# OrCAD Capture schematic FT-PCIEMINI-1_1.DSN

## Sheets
1 INDEX: title: 01-INDEX; rev: 1.1
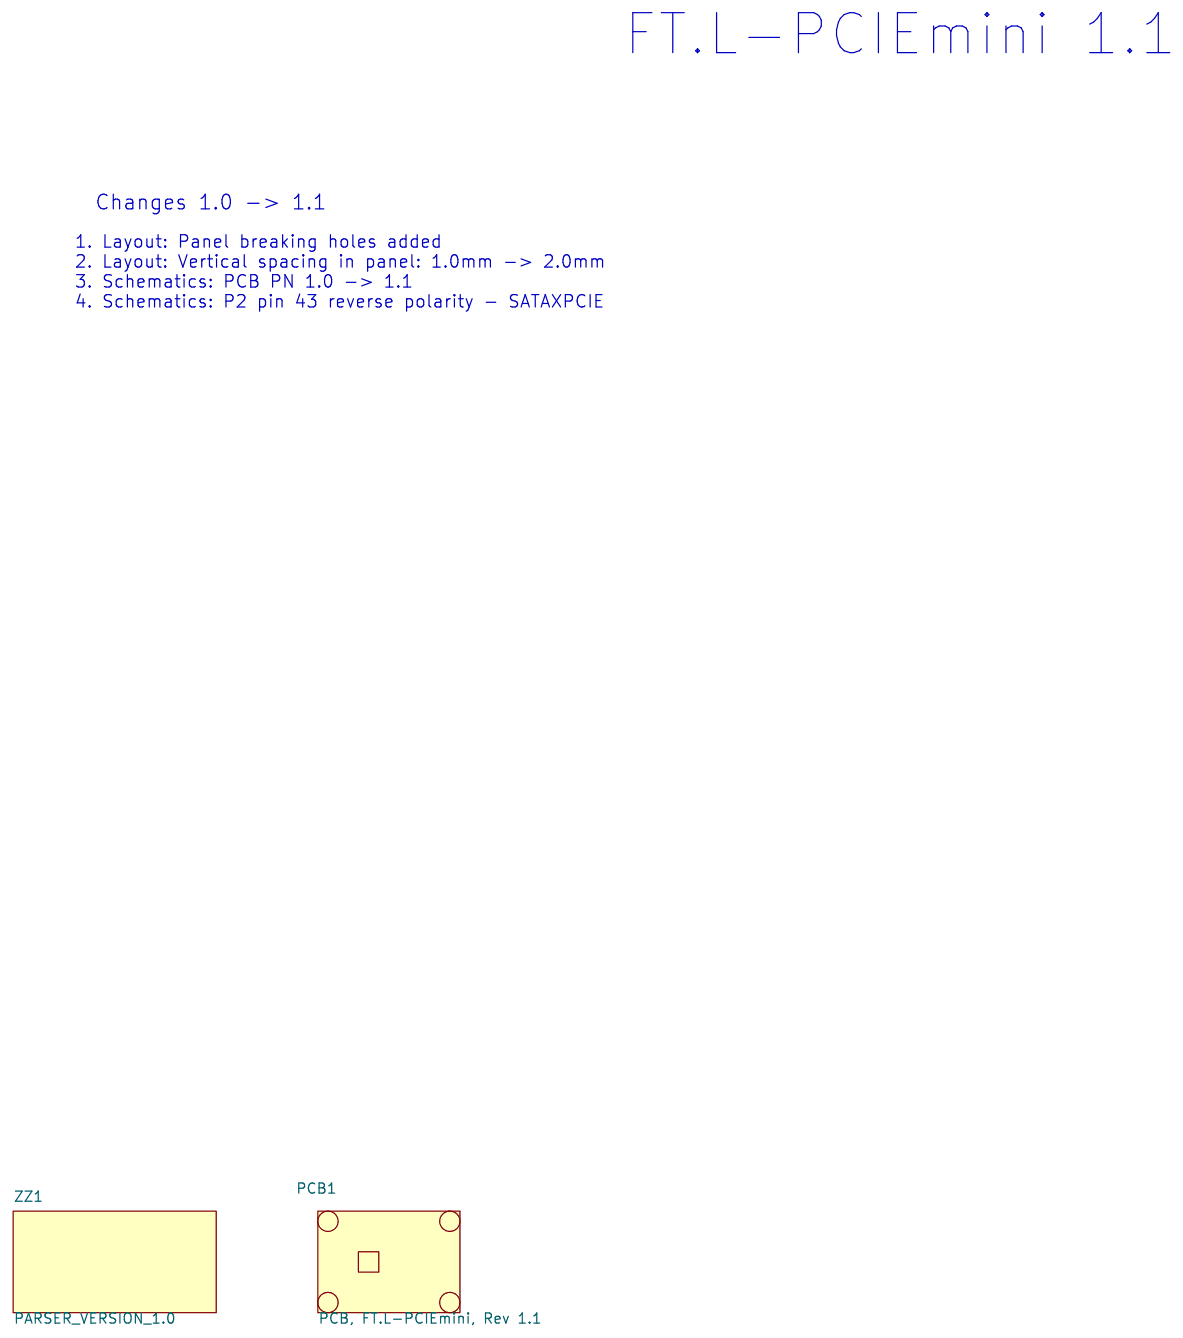
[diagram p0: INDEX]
2 TRIP: size A; title: 02-TRIP
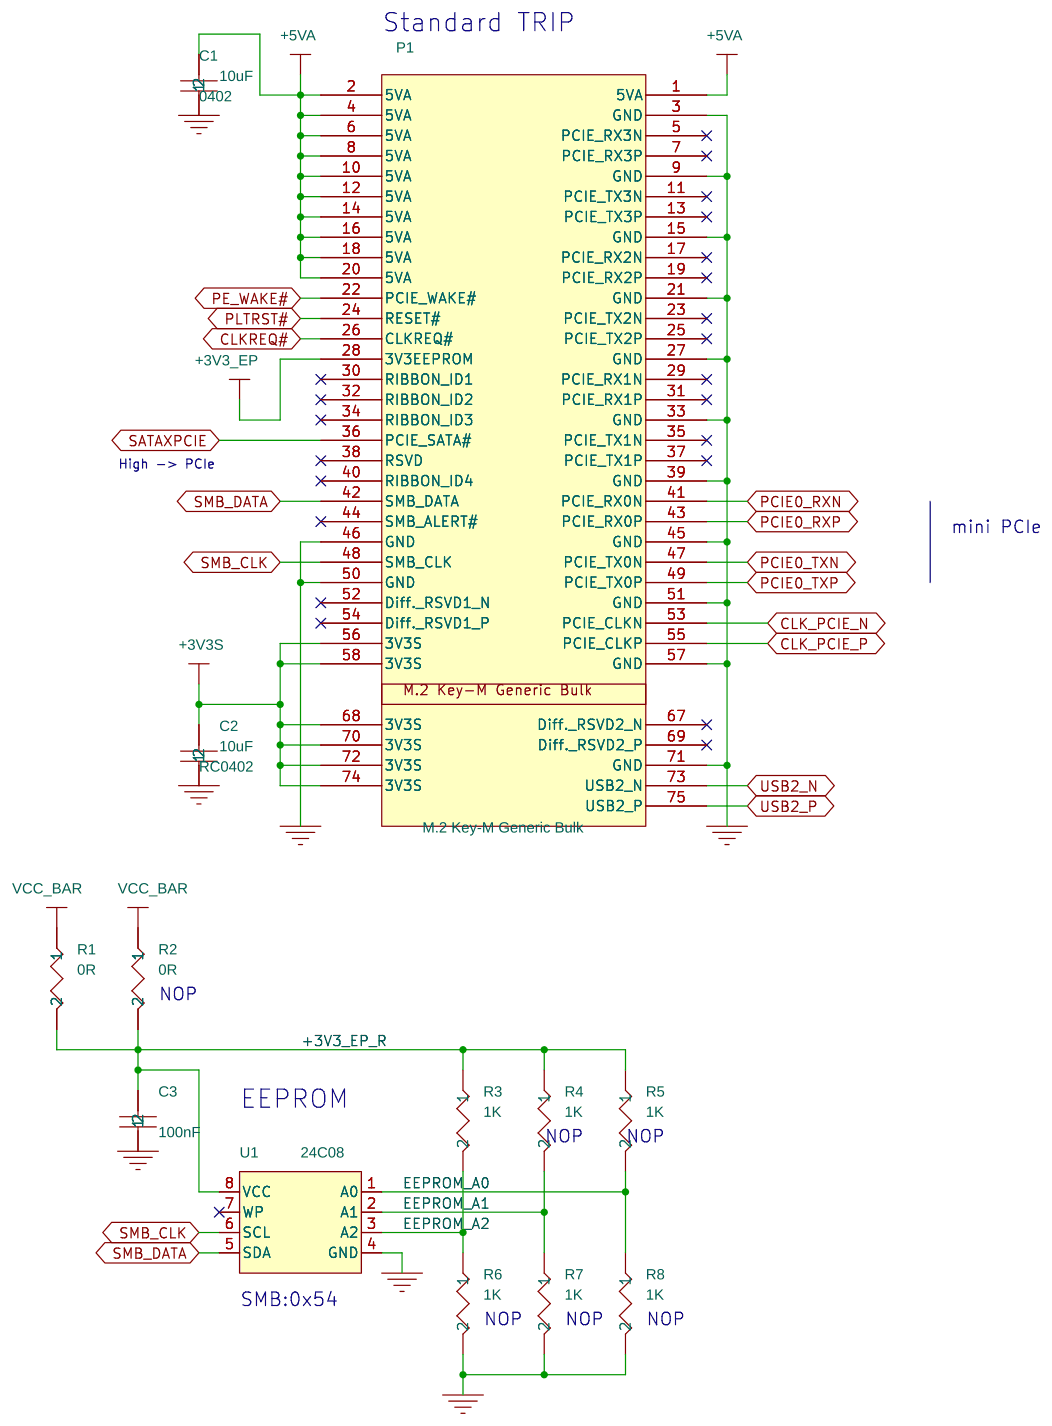
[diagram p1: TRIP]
3 miniPCIe/PWR: size A4; title: 04-M.2 Key B/E
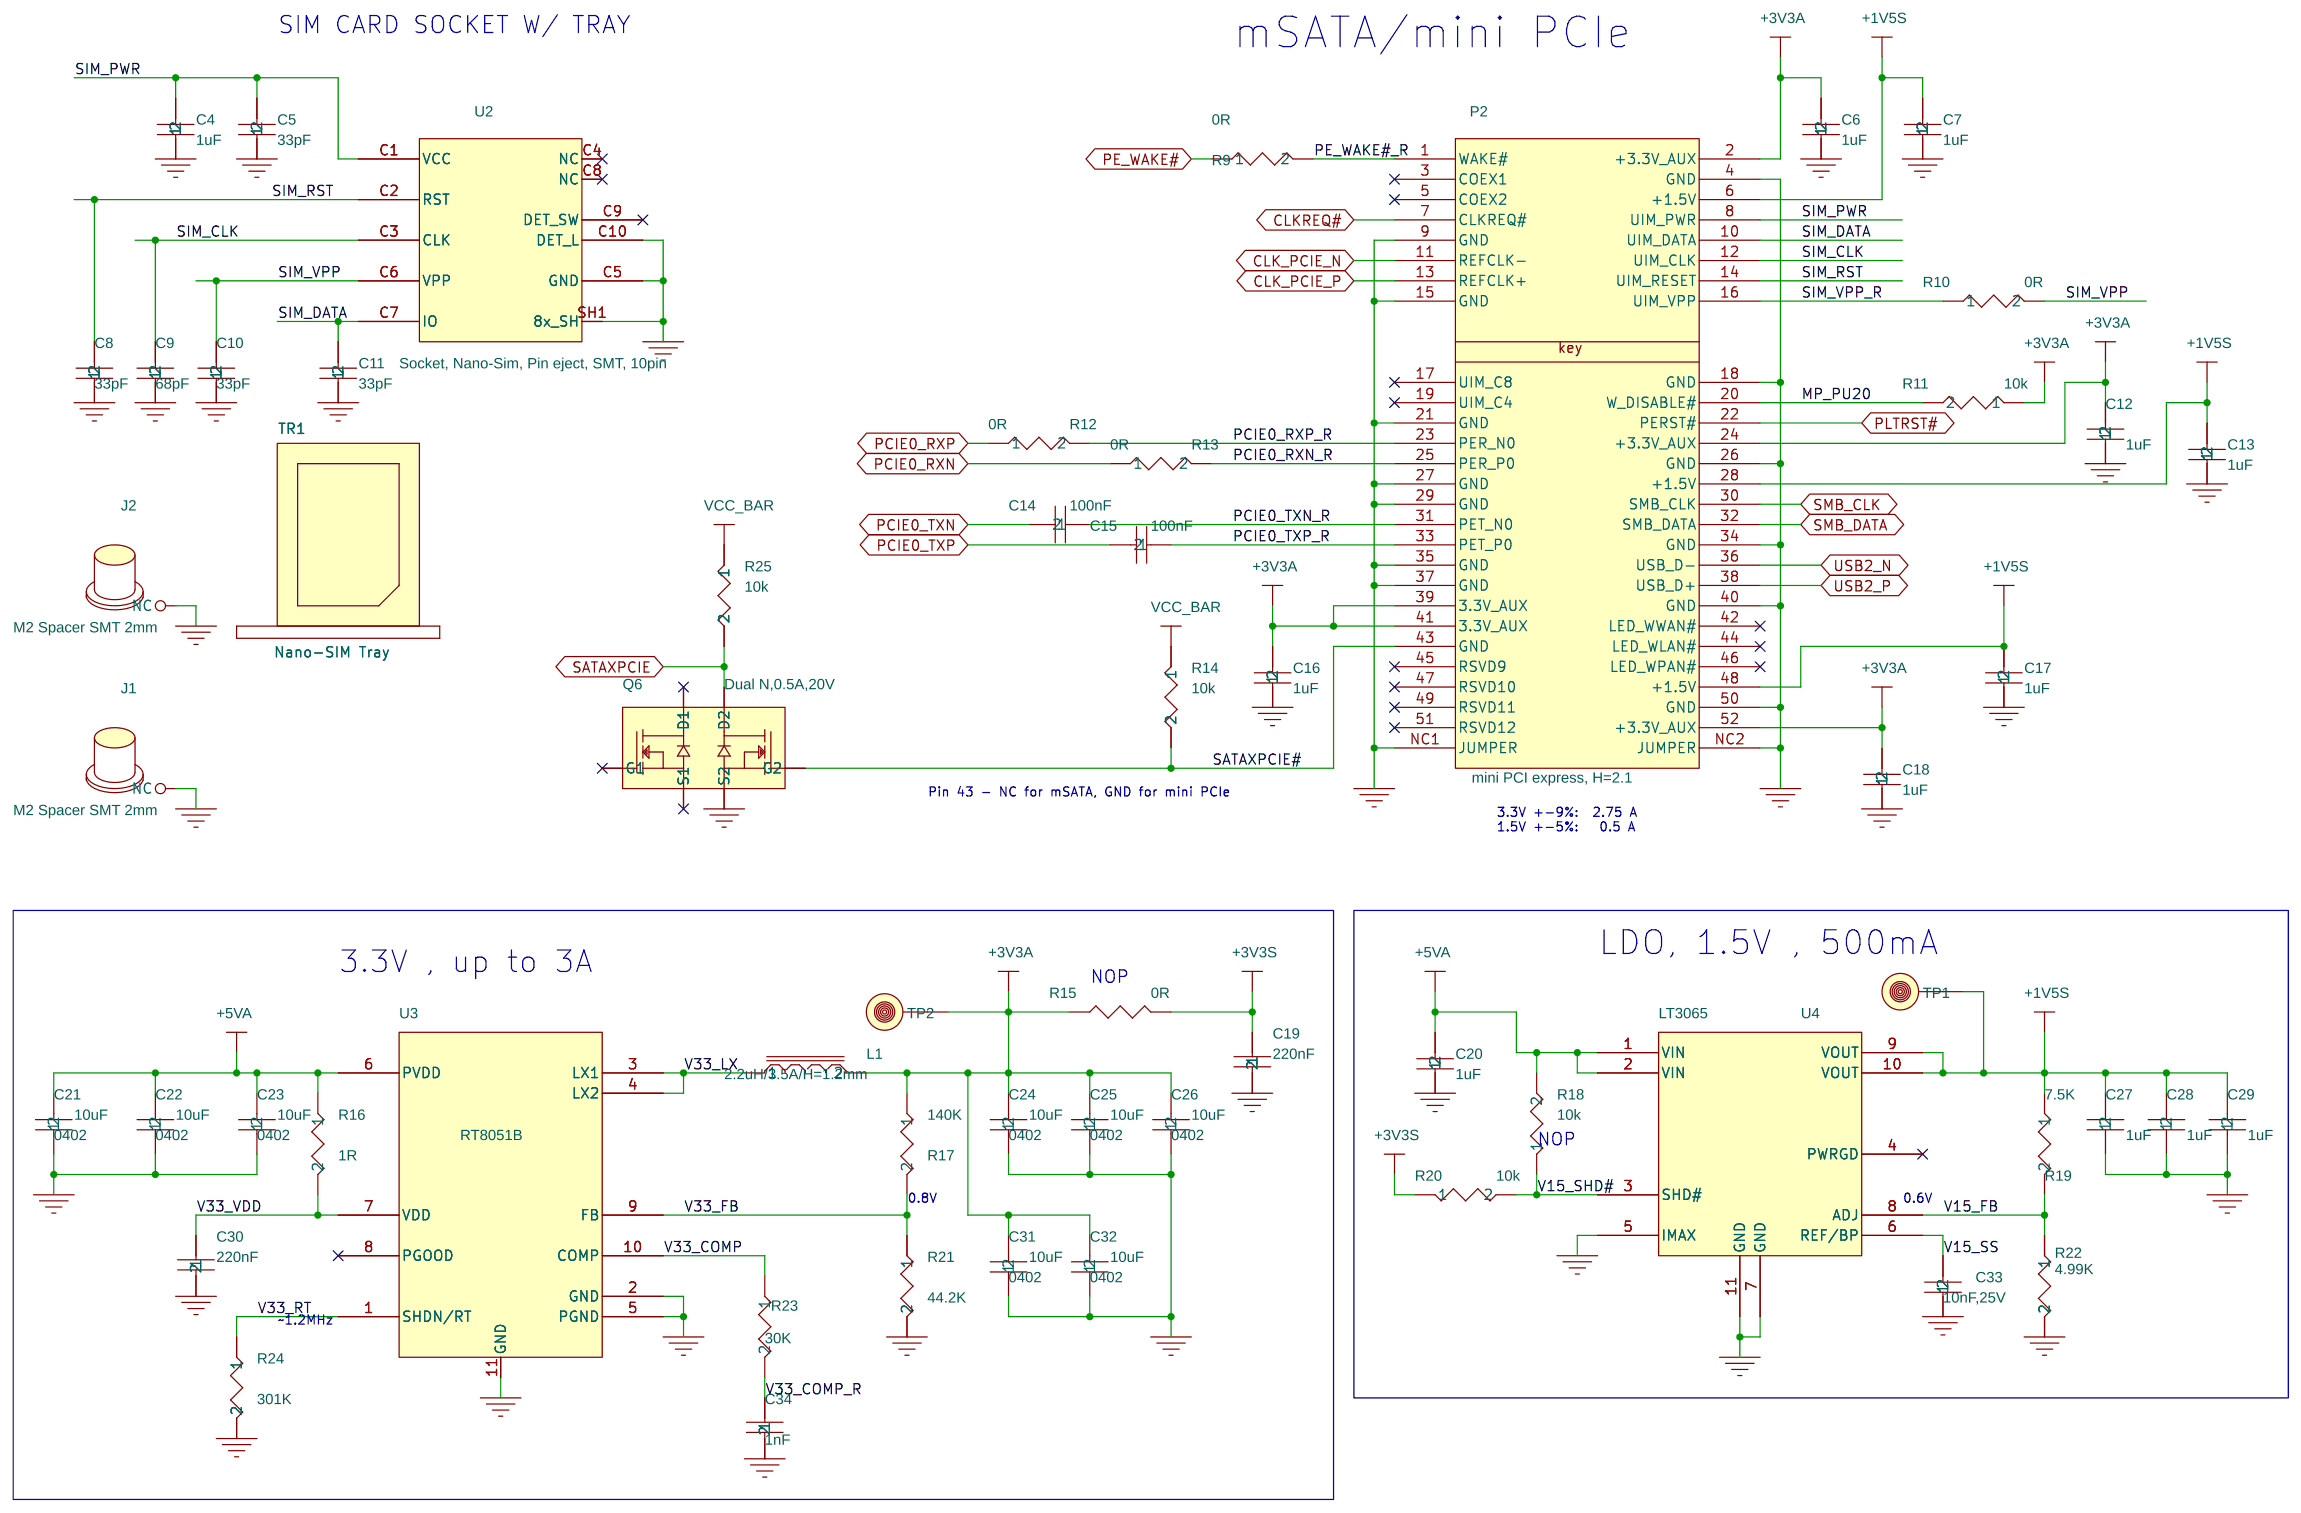
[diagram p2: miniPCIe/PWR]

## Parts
sheet INDEX
PCB1  PCB, FT.L-PCIEmini, Rev 1.1
ZZ1  PARSER_VERSION_1.0
sheet miniPCIe/PWR
C4  1uF  [RC0402]
C5  33pF  [RC0402]
C6  1uF  [RC0402]
C7  1uF  [RC0402]
C8  33pF  [RC0402]
C9  68pF  [RC0402]
C10  33pF  [RC0402]
C11  33pF  [RC0402]
C12  1uF  [RC0402]
C13  1uF  [RC0402]
C14  100nF  [RC0402]
C15  100nF  [RC0402]
C16  1uF  [RC0402]
C17  1uF  [RC0402]
C18  1uF  [RC0402]
C19  220nF  [RC0402]
C20  1uF  [RC0402]
C21  10uF  [0402]
C22  10uF  [0402]
C23  10uF  [0402]
C24  10uF  [0402]
C25  10uF  [0402]
C26  10uF  [0402]
C27  1uF  [RC0402]
C28  1uF  [RC0402]
C29  1uF  [RC0402]
C30  220nF  [RC0402]
C31  10uF  [0402]
C32  10uF  [0402]
C33  10nF,25V  [RC0402]
C34  1nF  [RC0402]
J1  M2 Spacer SMT 2mm  [SpacerM2H4SM]
J2  M2 Spacer SMT 2mm  [SpacerM2H4SM]
L1  2.2uH/3.5A/H=1.2mm  [IND4_3x4_7SM]
P2  mini PCI express, H=2.1  [MINI_PCIE_PAD]
Q6  Dual N,0.5A,20V  [SOT-563-6]
R9  0R  [RC0402]
R10  0R  [RC0402]
R11  10k  [RC0402]
R12  0R  [RC0402]
R13  0R  [RC0402]
R14  10k  [RC0402]
R15  0R  [RC0402]
R16  1R  [RC0402]
R17  140K  [RC0402]
R18  10k  [RC0402]
R19  7.5K  [RC0402]
R20  10k  [RC0402]
R21  44.2K  [RC0402]
R22  4.99K  [RC0402]
R23  30K  [RC0402]
R24  301K  [RC0402]
R25  10k  [RC0402]
TP1  TP
TP2  TP
TR1  Nano-SIM Tray
U2  Socket, Nano-Sim, Pin eject, SMT, 10pin  [SKT-MicroSIM6-SM]
U3  RT8051B  [DFN3x3-10]
U4  LT3065  [DFN3x3-10]
sheet TRIP
C1  10uF  [0402]
C2  10uF  [RC0402]
C3  100nF  [RC0402]
P1  M.2 Key-M Generic Bulk  [NGFF67P8HMkeySM]
R1  0R  [RC0402]
R2  0R  [RC0402]
R3  1K  [RC0402]
R4  1K  [RC0402]
R5  1K  [RC0402]
R6  1K  [RC0402]
R7  1K  [RC0402]
R8  1K  [RC0402]
U1  24C08  [MO-229VCED-2]

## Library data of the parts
PCB1 = SBC-iHSW_Rev_1.0: CLABCONF0: FT.L-PCIEmini; P/N: 188C03471U
ZZ1 = PARSER_VERSION_1.0: CLABCONF0: FT.L-PCIEmini
C4 = 15pF,_50V,_NPO,_5%,_0402_16: CLABCONF0: FT.L-PCIEmini; P/N: 151C10500S
C5 = 15pF,_50V,_NPO,_5%,_0402_11: CLABCONF0: FT.L-PCIEmini; P/N: 151K33000S
C6 = 15pF,_50V,_NPO,_5%,_0402_6: CLABCONF0: FT.L-PCIEmini; P/N: 151C10500S
C7 = 15pF,_50V,_NPO,_5%,_0402_7: CLABCONF0: FT.L-PCIEmini; P/N: 151C10500S
C8 = 15pF,_50V,_NPO,_5%,_0402_2: CLABCONF0: FT.L-PCIEmini; P/N: 151K33000S
C9 = 15pF,_50V,_NPO,_5%,_0402: CLABCONF0: FT.L-PCIEmini; P/N: 155068R00S
C10 = 15pF,_50V,_NPO,_5%,_0402_13: CLABCONF0: FT.L-PCIEmini; P/N: 151K33000S
C11 = 15pF,_50V,_NPO,_5%,_0402_9: CLABCONF0: FT.L-PCIEmini; P/N: 151K33000S
C12 = 15pF,_50V,_NPO,_5%,_0402_1: CLABCONF0: FT.L-PCIEmini; P/N: 151C10500S
C13 = 15pF,_50V,_NPO,_5%,_0402_15: CLABCONF0: FT.L-PCIEmini; P/N: 151C10500S
C14 = 100nF,_10V,_X7R,_10%,_0402_2: CLABCONF0: FT.L-PCIEmini; P/N: 151B10400S
C15 = 100nF,_10V,_X7R,_10%,_0402_7: CLABCONF0: FT.L-PCIEmini; P/N: 151B10400S
C16 = 15pF,_50V,_NPO,_5%,_0402_12: CLABCONF0: FT.L-PCIEmini; P/N: 151C10500S
C17 = 15pF,_50V,_NPO,_5%,_0402_8: CLABCONF0: FT.L-PCIEmini; P/N: 151C10500S
C18 = 15pF,_50V,_NPO,_5%,_0402_3: CLABCONF0: FT.L-PCIEmini; P/N: 151C10500S
C19 = 100nF,_10V,_X7R,_10%,_0402_6: CLABCONF0: FT.L-PCIEmini; P/N: 151C22400S
C20 = 15pF,_50V,_NPO,_5%,_0402_14: CLABCONF0: FT.L-PCIEmini; P/N: 151C10500S
C21 = 100nF,_10V,_X7R,_10%,_0402_9: CLABCONF0: FT.L-PCIEmini; P/N: 151B10600S
C22 = 100nF,_10V,_X7R,_10%,_0402_10: CLABCONF0: FT.L-PCIEmini; P/N: 151B10600S
C23 = 100nF,_10V,_X7R,_10%,_0402_3: CLABCONF0: FT.L-PCIEmini; P/N: 151B10600S
C24 = 100nF,_10V,_X7R,_10%,_0402_8: CLABCONF0: FT.L-PCIEmini; P/N: 151B10600S
C25 = 100nF,_10V,_X7R,_10%,_0402_12: CLABCONF0: FT.L-PCIEmini; P/N: 151B10600S
C26 = 100nF,_10V,_X7R,_10%,_0402_5: CLABCONF0: FT.L-PCIEmini; P/N: 151B10600S
C27 = 15pF,_50V,_NPO,_5%,_0402_4: CLABCONF0: FT.L-PCIEmini; P/N: 151C10500S
C28 = 15pF,_50V,_NPO,_5%,_0402_10: CLABCONF0: FT.L-PCIEmini; P/N: 151C10500S
C29 = 15pF,_50V,_NPO,_5%,_0402_5: CLABCONF0: FT.L-PCIEmini; P/N: 151C10500S
C30 = 100nF,_10V,_X7R,_10%,_0402: CLABCONF0: FT.L-PCIEmini; P/N: 151C22400S
C2 C31 = 100nF,_10V,_X7R,_10%,_0402_1: CLABCONF0: FT.L-PCIEmini; P/N: 151B10600S
C32 = 100nF,_10V,_X7R,_10%,_0402_4: CLABCONF0: FT.L-PCIEmini; P/N: 151B10600S
C33 = 100nF,_10V,_X7R,_10%,_0402_11: CLABCONF0: FT.L-PCIEmini; P/N: 151C10300S
C34 = 22nF,_10V,_X7R,_10%,_0402: CLABCONF0: FT.L-PCIEmini; P/N: 151D10200S
J1 J2 = Spacer_SMT,_M2,_4mm: CLABCONF0: FT.L-PCIEmini; P/N: 383B52020S
L1 = Ind,_2.2uH,_3A_5A,_58_mOhm: CLABCONF0: FT.L-PCIEmini; P/N: 147A2R206S
P2 = mini_PCIe_2: CLABCONF0: 182K05200S=FT.L-PCIEmini
Q6 = DUAL_N-MOSFET,_0.5A_20V: CLABCONF0: FT.L-PCIEmini
R9 = 0R_4: CLABCONF0: FT.L-PCIEmini
R10 = 0R_5: CLABCONF0: FT.L-PCIEmini
R11 = 1M_,5%,_0402_3: CLABCONF0: FT.L-PCIEmini; P/N: 161C10021S
R12 = 0R_3: CLABCONF0: FT.L-PCIEmini
R13 = 0R_2: CLABCONF0: FT.L-PCIEmini
R14 = 1M_,5%,_0402_4: CLABCONF0: FT.L-PCIEmini; P/N: 161C10021S
R15 = 10K,1%,0402,1_16W_0: CLABCONF0: NOP; P/N: 161C00005S
R16 = 4.02K,1%,0402_4: CLABCONF0: FT.L-PCIEmini; P/N: 161C1R001S
R17 = 4.02K,1%,0402_3: CLABCONF0: FT.L-PCIEmini; P/N: 161C14031S
R18 = 1M_,5%,_0402: CLABCONF0: NOP; P/N: 161C10021S
R19 = 0R: CLABCONF0: FT.L-PCIEmini; P/N: 161C75011S
R20 = 1M_,5%,_0402_2: CLABCONF0: FT.L-PCIEmini; P/N: 161C10021S
R21 = 4.02K,1%,0402_2: CLABCONF0: FT.L-PCIEmini; P/N: 161C44221S
R22 = 0R_1: CLABCONF0: FT.L-PCIEmini; P/N: 161C49911S
R23 = 4.02K,1%,0402_1: CLABCONF0: FT.L-PCIEmini; P/N: 161C30021S
R24 = 4.02K,1%,0402: CLABCONF0: FT.L-PCIEmini; P/N: 161C30131S
R25 = 1M_,5%,_0402_1: CLABCONF0: FT.L-PCIEmini; P/N: 161C10021S
TP1 = TP_SMT: CLABCONF0: NOP
TP2 = TP_SMT: CLABCONF0: FT.L-PCIEmini
TR1 = Nano-SIM_Tray: CLABCONF0: FT.L-PCIEmini; P/N: 190Z00000
U2 = Nano-SIM_Socket_pin-eject: CLABCONF0: FT.L-PCIEmini; P/N: 190I01000S
U3 = RT8051B_4: CLABCONF0: FT.L-PCIEmini; P/N: 123V5R004S
U4 = LT3065_0: CLABCONF0: FT.L-PCIEmini; P/N: 123M0R601S
C1 = 100nF,_10V,_X7R,_10%,_0402: CLABCONF0: FT.L-PCIEmini; P/N: 151B10600S
C3 = 15pF,_50V,_NPO,_5%,_0402: CLABCONF0: FT.L-PCIEmini; P/N: 151B10400S
P1 = M.2_Key-M_Generic_Bulk: CLABCONF0: FT.L-PCIEmini; P/N: 182K06700S
R1 = 348R,1%,0402,1_16W_6: CLABCONF0: FT.L-PCIEmini; P/N: 161C00005S
R2 = 348R,1%,0402,1_16W_5: CLABCONF0: NOP; P/N: 161C00005S
R3 = 348R,1%,0402,1_16W_1: CLABCONF0: FT.L-PCIEmini; P/N: 161C10011S
R4 = 348R,1%,0402,1_16W_2: CLABCONF0: NOP; P/N: 161C10011S
R5 = 348R,1%,0402,1_16W: CLABCONF0: NOP; P/N: 161C10011S
R6 = 348R,1%,0402,1_16W_7: CLABCONF0: NOP; P/N: 161C10011S
R7 = 348R,1%,0402,1_16W_4: CLABCONF0: NOP; P/N: 161C10011S
R8 = 348R,1%,0402,1_16W_3: CLABCONF0: NOP; P/N: 161C10011S
U1 = 24C02,_serial_EE,_2KB,_I2C: CLABCONF0: FT.L-PCIEmini; P/N: 111S31000S

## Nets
+1V5S: C7.2 C13.2 C17.2 C27.2 C28.2 C29.2 P2.6(+1.5V) P2.28(+1.5V) P2.48(+1.5V) R19.1 TP1.1 U4.9(VOUT) U4.10(VOUT)
+3V3_EP: P1.28(3V3EEPROM) R1.1
+3V3_EP_R: C3.2 R1.2 R2.2 R3.1 R4.1 R5.1 U1.8(VCC)
+3V3A: C6.2 C12.2 C16.2 C18.2 C24.2 C25.2 C26.2 C31.2 C32.2 L1.2 P2.2(+3.3V_AUX) P2.24(+3.3V_AUX) P2.39(3.3V_AUX) P2.41(3.3V_AUX) P2.52(+3.3V_AUX) R11.1 R15.1 R17.1 TP2.1
+3V3S: C2.2 C19.1 P1.56(3V3S) P1.58(3V3S) P1.68(3V3S) P1.70(3V3S) P1.72(3V3S) P1.74(3V3S) R2.1 R14.1 R15.2 R20.1 R25.1
+5VA: C1.2 C20.2 C21.2 C22.2 C23.2 P1.1(5VA) P1.2(5VA) P1.4(5VA) P1.6(5VA) P1.8(5VA) P1.10(5VA) P1.12(5VA) P1.14(5VA) P1.16(5VA) P1.18(5VA) P1.20(5VA) R16.1 R18.2 U3.6(PVDD) U4.1(VIN) U4.2(VIN)
GND: C1.1 C2.1 C3.1 C4.1 C5.1 C6.1 C7.1 C8.1 C9.1 C10.1 C11.1 C12.1 C13.1 C16.1 C17.1 C18.1 C19.2 C20.1 C21.1 C22.1 C23.1 C24.1 C25.1 C26.1 C27.1 C28.1 C29.1 C30.2 C31.1 C32.1 C33.1 C34.2 J1.NC J2.NC P1.3(GND) P1.9(GND) P1.15(GND) P1.21(GND) P1.27(GND) P1.33(GND) P1.39(GND) P1.45(GND) P1.46(GND) P1.50(GND) P1.51(GND) P1.57(GND) P1.71(GND) P2.4(GND) P2.9(GND) P2.15(GND) P2.18(GND) P2.21(GND) P2.26(GND) P2.27(GND) P2.29(GND) P2.34(GND) P2.35(GND) P2.37(GND) P2.40(GND) P2.50(GND) P2.NC1(JUMPER) P2.NC2(JUMPER) Q6.4(S2) R6.2 R7.2 R8.2 R21.2 R22.2 R24.2 U1.4(GND) U2.C5(GND) U2.C10(DET_L) U2.SH1(8x_SH) U3.2(GND) U3.5(PGND) U3.11(GND) U4.5(IMAX) U4.7(GND) U4.11(GND)
V15_FB: R19.2 R22.1 U4.8(ADJ)
V15_SHD#: R18.1 R20.2 U4.3(SHD#)
V15_SS: C33.2 U4.6(REF/BP)
V33_COMP: R23.1 U3.10(COMP)
V33_COMP_R: C34.1 R23.2
V33_FB: R17.2 R21.1 U3.9(FB)
V33_LX: L1.1 U3.3(LX1) U3.4(LX2)
V33_RT: R24.1 U3.1(SHDN/RT)
V33_VDD: C30.1 R16.2 U3.7(VDD)
CLK_PCIE_N: P1.53(PCIE_CLKN) P2.11(REFCLK-)
CLK_PCIE_P: P1.55(PCIE_CLKP) P2.13(REFCLK+)
CLKREQ#: P1.26(CLKREQ#) P2.7(CLKREQ#)
EEPROM_A0: R5.2 R8.1 U1.1(A0)
EEPROM_A1: R4.2 R7.1 U1.2(A1)
EEPROM_A2: R3.2 R6.1 U1.3(A2)
MP_PU20: P2.20(W_DISABLE#) R11.2
PCIE0_RXN: P1.41(PCIE_RX0N) R13.1
PCIE0_RXN_R: P2.25(PER_P0) R13.2
PCIE0_RXP: P1.43(PCIE_RX0P) R12.1
PCIE0_RXP_R: P2.23(PER_N0) R12.2
PCIE0_TXN: C14.2 P1.47(PCIE_TX0N)
PCIE0_TXN_R: C14.1 P2.31(PET_N0)
PCIE0_TXP: C15.2 P1.49(PCIE_TX0P)
PCIE0_TXP_R: C15.1 P2.33(PET_P0)
PE_WAKE#: P1.22(PCIE_WAKE#) R9.1
PE_WAKE#_R: P2.1(WAKE#) R9.2
PLTRST#: P1.24(RESET#) P2.22(PERST#)
SATAXPCIE: P1.36(PCIE_SATA#) Q6.3(D2) R25.2
SATAXPCIE#: P2.43(GND) Q6.5(G2) R14.2
SIM_CLK: C9.2 P2.12(UIM_CLK) U2.C3(CLK)
SIM_DATA: C11.2 P2.10(UIM_DATA) U2.C7(IO)
SIM_PWR: C4.2 C5.2 P2.8(UIM_PWR) U2.C1(VCC)
SIM_RST: C8.2 P2.14(UIM_RESET) U2.C2(RST)
SIM_VPP: C10.2 R10.2 U2.C6(VPP)
SIM_VPP_R: P2.16(UIM_VPP) R10.1
SMB_CLK: P1.48(SMB_CLK) P2.30(SMB_CLK) U1.6(SCL)
SMB_DATA: P1.42(SMB_DATA) P2.32(SMB_DATA) U1.5(SDA)
USB2_N: P1.73(USB2_N) P2.36(USB_D-)
USB2_P: P1.75(USB2_P) P2.38(USB_D+)

Not connected (* = marked no-connect by the designer): P1 5(PCIE_RX3N)* 7(PCIE_RX3P)* 11(PCIE_TX3N)* 13(PCIE_TX3P)* 17(PCIE_RX2N)* 19(PCIE_RX2P)* 23(PCIE_TX2N)* 25(PCIE_TX2P)* 29(PCIE_RX1N)* 30(RIBBON_ID1)* 31(PCIE_RX1P)* 32(RIBBON_ID2)* 34(RIBBON_ID3)* 35(PCIE_TX1N)* 37(PCIE_TX1P)* 38(RSVD)* 40(RIBBON_ID4)* 44(SMB_ALERT#)* 52(Diff._RSVD1_N)* 54(Diff._RSVD1_P)* 67(Diff._RSVD2_N)* 69(Diff._RSVD2_P)*; P2 3(COEX1)* 5(COEX2)* 17(UIM_C8)* 19(UIM_C4)* 42(LED_WWAN#)* 44(LED_WLAN#)* 45(RSVD9)* 46(LED_WPAN#)* 47(RSVD10)* 49(RSVD11)* 51(RSVD12)*; Q6 1(S1)* 2(G1)* 6(D1)*; U1 7(WP)*; U2 C4(NC)* C8(NC)* C9(DET_SW)*; U3 8(PGOOD)*; U4 4(PWRGD)*

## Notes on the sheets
sheet 1
- FT.L-PCIEmini 1.1
- Changes 1.0 -> 1.1
- 1. Layout: Panel breaking holes added
  2. Layout: Vertical spacing in panel: 1.0mm -> 2.0mm
  3. Schematics: PCB PN 1.0 -> 1.1
  4. Schematics: P2 pin 43 reverse polarity - SATAXPCIE
sheet 2
- Standard TRIP
- High -> PCIe
- mini PCIe
- NOP
- EEPROM
- NOP
- NOP
- SMB:0x54
- NOP
- NOP
- NOP
sheet 3
- SIM CARD SOCKET W/ TRAY
- mSATA/mini PCIe
- Pin 43 - NC for mSATA, GND for mini PCIe
- 3.3V +-9%:  2.75 A
  1.5V +-5%:   0.5 A
- LDO, 1.5V , 500mA
- 3.3V , up to 3A
- NOP
- NOP
- 0.8V
- 0.6V
- ~1.2MHz
